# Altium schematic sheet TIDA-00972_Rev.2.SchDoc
size 431 x 279 mm; Date: Not shown in title block; ApprovedBy: Not shown in title block; CheckedBy: Not shown in title block; Author: Not shown in title block; CompanyName: Not shown in title block; Engineer: Not shown in title block; Organization: Not shown in title block; Address1: Not shown in title block; Address2: Not shown in title block; Address3: Not shown in title block; Address4: Not shown in title block; DocumentNumber: 1; Revision: Use project parameter SCH_Rev; SheetNumber: 2; SheetTotal: 3; PageSetup: Record=PageOptions¦CenterHorizontal=True¦CenterVertical=True¦PrintScale=1.00¦XCorrection=1.00¦YCorrection=1.00¦PrintKind=0¦BorderSize=5000000¦LeftOffset=0¦BottomOffset=0¦Orientation=2¦PaperLength=1000¦PaperWidth=1000¦Scale=100¦PaperSource=15¦PrintQuality=600¦MediaType=1¦DitherType=10¦PaperKind=Letter¦PrintScaleMode=1
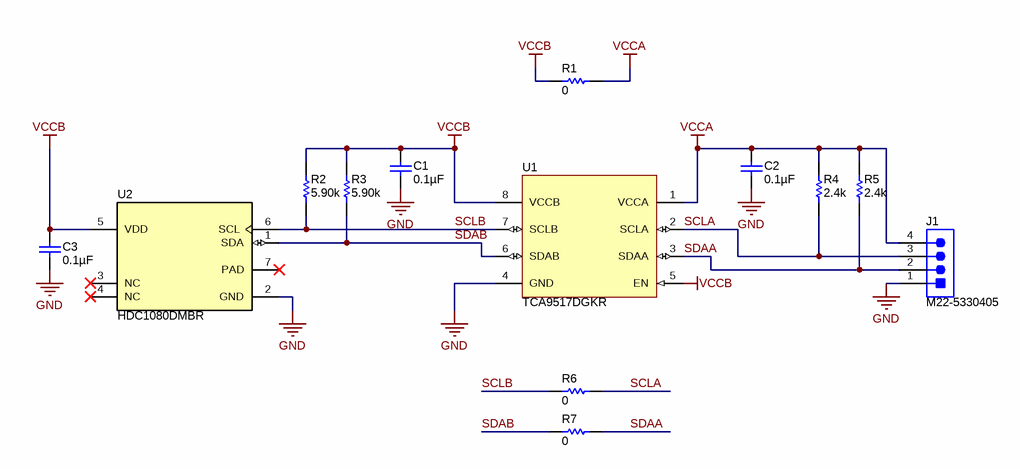
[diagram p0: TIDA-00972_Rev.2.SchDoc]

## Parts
C1  ValueDisplayed: 0.1µF  [0402S]  (hidden comment: 885012105016)
C2  ValueDisplayed: 0.1µF  [0402S]  (hidden comment: 885012105016)
C3  ValueDisplayed: 0.1µF  [0402S]  (hidden comment: 885012105016)
J1  M22-5330405  [Harwin_M22-5330405]
R1  ValueDisplayed: 0  [0402S]  (hidden comment: RC0402JR-070RL)
R2  ValueDisplayed: 5.90k  [0402S]  (hidden comment: CRCW04025K90FKED)
R3  ValueDisplayed: 5.90k  [0402S]  (hidden comment: CRCW04025K90FKED)
R4  ValueDisplayed: 2.4k  [0402S]  (hidden comment: CRCW04022K40JNED)
R5  ValueDisplayed: 2.4k  [0402S]  (hidden comment: CRCW04022K40JNED)
R6  ValueDisplayed: 0  [0402S]  (hidden comment: RC0402JR-070RL)
R7  ValueDisplayed: 0  [0402S]  (hidden comment: RC0402JR-070RL)
U1  TCA9517DGKR  [DGK0008A_N]
U2  HDC1080DMBR  [DMB0006A]

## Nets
GND: C1.2 C2.2 C3.2 J1.1 U1.4(GND) U2.2(GND)
VCCA: C2.1 J1.4 R1.2 R4.2 R5.2 U1.1(VCCA)
VCCB: C1.1 C3.1 R1.1 R2.2 R3.2 U1.5(EN) U1.8(VCCB) U2.5(VDD)
SCLA: J1.3 R4.1 R6.2 U1.2(SCLA)
SCLB: R2.1 R6.1 U1.7(SCLB) U2.6(SCL)
SDAA: J1.2 R5.1 R7.2 U1.3(SDAA)
SDAB: R3.1 R7.1 U1.6(SDAB) U2.1(SDA)

Not connected (* = marked no-connect by the designer): U2 3(NC)* 4(NC)* 7(PAD)*

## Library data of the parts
C1-C3 = 885012105016: CAP, CERM, 0.1 µF, 16 V, +/- 20%, X5R, 0402; Manufacturer: Wurth Elektronik; Polarized: N; CompType: Capacitor; Value: 0.1uF; U/M: EA; Cap_F: 0.0000001; Tolerance_%: 20; Value1: Unknown; VDC_V: 16; Value2: 16V; TaMin_C: -55; TaMax_C: 85; Cap_Case: 0402; AEC Category: Q200
J1 = M22-5330405: Header, 2mm, 4x1, Gold, Black, R/A, SMT; Manufacturer: Harwin; SymbolCreator: a0412235; Pitch_mm: 2; Gender: Male; Row_Count: 1
R1 R6 R7 = RC0402JR-070RL: RES, 0, 5%, 0.063 W, 0402; Manufacturer: Yageo America; CompType: Resistor; Value: 0; Value_Code: 0000; Tolerance_%: 5; Power_W: 0.063; Value2: 0.063W; VDC_V: 50; TempCo: 200 ppm/C; EIA_Code: E24; U/M: EA; AEC Category: Q200
R2 R3 = CRCW04025K90FKED: RES, 5.90 k, 1%, 0.063 W, 0402; Manufacturer: Vishay-Dale; CompType: Resistor; Value: 5.90k; Res_ohm: 5900; Value_Code: 5k90; Tolerance_%: 1; Power_W: 0.063; Value2: 0.063W; VDC_V: 50; TempCo: 100 ppm/C; EIA_Code: E96; U/M: EA; AEC Category: Q200
R4 R5 = CRCW04022K40JNED: RES, 2.4 k, 5%, 0.063 W, 0402; Manufacturer: Vishay-Dale; CompType: Resistor; Value: 2.4k; Res_ohm: 2400; Value_Code: 2k40; Tolerance_%: 5; Power_W: 0.063; Value2: 0.063W; VDC_V: 50; TempCo: 200 ppm/C; EIA_Code: E24; U/M: EA; AEC Category: Q200
U1 = TCA9517DGKR: LEVEL-TRANSLATING I2C BUS REPEATER, DGK0008A; Manufacturer: Texas Instruments; SymbolCreator: a0411947; CompType: IC; U/M: EA
U2 = HDC1080DMBR: Low Power, High Accuracy Digital Humidity Sensor with Temperature Sensor, DMB0006A; Alternate PartNumber: HDC1080DMBT; Manufacturer: Texas Instruments; SymbolCreator: a0411947; CompType: IC; U/M: EA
